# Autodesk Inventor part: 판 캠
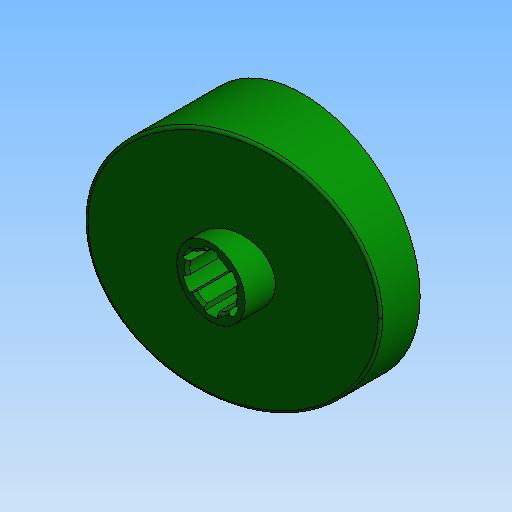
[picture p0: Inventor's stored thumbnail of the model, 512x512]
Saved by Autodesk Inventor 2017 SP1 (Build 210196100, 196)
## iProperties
Created: 2021-07
Part Number: 판 캠
Document SubType Name: 모델링
Designer: mdu
Material: 알루미늄 6061
Density: 2.71 g/cm^3
Mass: 235.299 g
Surface Area: 331.301 cm^2
Volume: 86.8262 cm^3
Appearance: 진녹색
변환 표준: STEP AP214IS
파일 이름: C:\Users\SeoGD\Desktop\?쒗뿕\??stp
전처리기: Build: 253, Release: 2010 SP1 - Date: Wed 07/29/2009
전송 단위: 밀리미터
불확실성: 0.01
Author: mdu
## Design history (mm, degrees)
node "작업 평면4"
sketch "스케치1"
  geometry: C1 r 44.5 at (0, 0); 1 further point
  constraints: 1 centre point, 1 coincident
  dimensions: "d25" = 89 diameter of C1
extrude "돌출1" new body sketch "스케치1" distance "d1" = 40; taper "d2" = 0 deg
sketch "스케치2"
  geometry: L1 (-44.5, 15)-(44.5, 38.847); L2 (-44.5, 0)-(-44.5, 40) reference; L3 (-44.5, 40)-(44.5, 40) reference; L4 (44.5, 0)-(44.5, 40) reference; 1 further point
  constraints: 2 end point, 2 point on line
  dimensions: "d26" = 15 distance of L2.start L1.start; "d27" = 75 deg angle of L1 L2
extrude "돌출2" cut sketch "스케치2" stored distance "d5" = 40; taper "d6" = 0 deg
node "작업 평면1"
sketch "스케치3"
  geometry: C1 r 13 at (0, 0); 1 further point
  constraints: 1 centre point, 1 coincident
  dimensions: "d9" = 26 diameter of C1
extrude "돌출3" join sketch "스케치3" distance "d10" = 38; taper "d11" = 0 deg
hole "구멍1" diameter "d14" = 18; stored, may be unused: countersink angle "d18" = 90 deg, drill point angle "d20" = 118 deg; dims "d12" = 10, "d13" = 10, "d15" = 6, "d16" = 4, "d17" = 2, "d19" = 8
feature "쉘2" dims "d29" = 5
sketch "스케치6"
  geometry: C1 r 17.5 at (0, 0); C2 r 14 at (0, 0) reference; 1 further point
  constraints: 1 centre point, 1 coincident
  dimensions: "d28" = 35 diameter of C1
extrude "돌출4" join sketch "스케치6" stored distance "d30" = 38; taper "d31" = 0 deg
fillet "모깎기1" dims "d32" = 3
chamfer "모따기1" distance "d21" = 1; stored, may be unused: second distance "d22" = 2, angle "d23" = 45 deg
sketch "스케치7"
  geometry: L1 (-12.374, 12.374)-(-27.931, 27.931); A1 r 39.5 centre (0, 0) between (-27.931, 27.931) and (0, 39.5) reference; 2 further points
  constraints: 2 end point, 2 point on circle, 1 point on line, 1 vertical alignment, 2 other
  dimensions: "d33" = 45 deg dimension on point (0, 0) L1.start A1.end
feature "리브1" sketch "스케치7" dims "d34" = 5, "d35" = 1, "d36" = 0
fillet "모깎기2" dims "d37" = 3
sketch "스케치8"
  geometry: L1 (2.5, 10.712)-(2.5, 8.646); L2 (-2.5, 10.712)-(-2.5, 8.646); A1 r 11 centre (0, 0) between (2.5, 10.712) and (-2.5, 10.712); A2 r 9 centre (0, 0) between (2.5, 8.646) and (-2.5, 8.646) reference; 1 further point
  constraints: 4 end point, 4 point on circle, 2 parallel, 1 centre point, 1 coincident, 1 vertical
  dimensions: "d41" = 22 diameter of A1; "d42" = 5 distance between parallel lines of L1 L2
extrude "돌출5" cut sketch "스케치8" stored distance "d43" = 38; taper "d44" = 0 deg
fillet "모깎기3" dims "d48" = 1
node "솔리드1"
node "솔리드 본체"
node "곡면 본체"
pattern_circular "원형 패턴1" dims angle "d39" = 360 deg
pattern_circular "원형 패턴2" dims angle "d46" = 360 deg
node "솔리드2"
